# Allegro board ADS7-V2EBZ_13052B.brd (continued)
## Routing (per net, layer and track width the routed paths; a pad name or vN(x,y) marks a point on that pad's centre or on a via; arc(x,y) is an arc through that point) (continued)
UNNAMED_22_RES_I263_N2: length 4.7
  TOP w0.14: R52.2 201.55,142.37 v1(200.91,143)
  BOTTOM w0.14: v1(200.91,143) 199.64,143 198.5,144.15 Q11.3
UNNAMED_22_RES_I265_N2: length 1.8
  TOP w0.14: R61.2 v1(17.27,132.84)
  BOTTOM w0.14: Q12.3 v1(17.27,132.84)
UNNAMED_24_CAP_I8_N2: length 6.3
  BOTTOM w0.203: C164.2 90.52,126.81 U39.1 ; C164.2 90.81,126.71 90.81,128.52 ; C164.2 91.06,126.28 R232.2
UNNAMED_24_CAP_I26_N2: length 6.6
  TOP w0.14: C134.2 156.55,29.85 158.37,29.85 158.64,30.12 U35.1 ; C134.2 155.96,29.76 R177.2 ; C134.2 156.21,30.19 R664.2
UNNAMED_24_ICTPS51200_I1_EN: length 4.8
  BOTTOM w0.14: R222.1 R559.2 R558.1 86.88,130.8 U39.7
UNNAMED_24_ICTPS51200_I33_EN: length 5.3
  TOP w0.14: R658.2 R170.1 R660.1 160.14,34.28 U35.7
UNNAMED_25_74LVC1G17_I357_A: length 8.2
  TOP w0.14: v1(171.45,121.54) 171.96,121.54 CR1.C
  BOTTOM w0.14: 172.47,120.52 172.47,119.8 R233.1 ; 172.47,120.52 v1(171.45,121.54) R224.2 ; 172.47,120.52 U40.2
UNNAMED_25_CAP_I36_N2: length 13.1
  TOP w0.14: C142.2 S6.3 S6.4 105.92,18.62 R193.1 104.27,21.08
UNNAMED_25_CAP_I49_N2: length 9
  BOTTOM w0.14: S3.4 105.87,28.7 R191.1 C141.2 ; C141.2 101.47,27.3 100.71,26.54 ; C141.2 99.51,28.7 S3.3
UNNAMED_25_CAP_I423_N2: length 13.9
  TOP w0.14: R175.2 207.77,34.29 208.66,35.18 208.66,37.34 R169.1 C130.2 R168.2 204.09,39.12 U33.6
UNNAMED_25_CN3P_I305_N1: length 8.3
  TOP w0.14: D3.A 163.53,125.78 163.7,125.6 P4.1
  BOTTOM w0.14: Q13.3 163.58,123.95 P4.1
UNNAMED_25_CN3P_I305_N3: length 4.2
  BOTTOM w0.14: P4.3 168.91,123.95 R224.1 R234.2
UNNAMED_25_CNBNC5P_I329_CNTR: length 4.1
  TOP w0.14: R151.2 J6.1
UNNAMED_25_CNBNC5P_I336_CNTR: length 5.5
  TOP w0.14: 207.14,75.95 J5.1
UNNAMED_25_CNBNC5P_I370_CNTR: length 8.6
  TOP w0.14: J3.1 209.42,45.47 208.66,44.7 C127.2
UNNAMED_25_CNBNC5P_I378_CNTR: length 4.8
  TOP w0.14: J4.1 R175.1
UNNAMED_25_DIOLED_I452_P: length 1.7
  TOP w0.14: R176.1 DS8.A
UNNAMED_25_DIOLED_I458_P: length 1.7
  TOP w0.14: R203.1 DS1.A
UNNAMED_25_DIOLED_I459_P: length 1.7
  TOP w0.14: R202.1 DS2.A
UNNAMED_25_DIOLED_I460_P: length 1.7
  TOP w0.14: R201.1 DS3.A
UNNAMED_25_DIOLED_I461_P: length 1.7
  TOP w0.14: R196.1 DS4.A
UNNAMED_25_DIOLED_I462_P: length 1.7
  TOP w0.14: R195.1 DS5.A
UNNAMED_25_DIOLED_I463_P: length 1.7
  TOP w0.14: DS6.A R194.1
UNNAMED_25_ICFXL4245_I446_B7: length 73.5
  TOP w0.14: v1(155.57,14.99) 155.57,15.75 155.31,16.01 U37.14 ; v1(89.66,25.15) R176.2
  L3_SIGNAL w0.095: v1(155.57,14.99) 119,14.99 117.98,13.97 109.86,13.97 107.19,16.64 103,16.64 96.27,23.37 92.96,23.37 91.19,25.15 v1(89.66,25.15)
UNNAMED_25_ICICS85411_I427_NQ0: length 3.7
  TOP w0.102: U33.2 195.94,40.39 195.45,40.87 194.89,40.87 194.42,41.34 194.25,41.34 R162.1
UNNAMED_25_ICICS85411_I427_NQ1: length 3.7
  TOP w0.102: U33.4 195.99,37.85 195.47,38.37 195.18,38.37 194.79,37.97 194.44,37.97 R167.1
UNNAMED_25_ICICS85411_I427_Q0: length 3.7
  TOP w0.102: R161.1 194.27,41.57 194.51,41.57 194.99,41.1 195.4,41.1 195.96,41.66 U33.1
UNNAMED_25_ICICS85411_I427_Q1: length 3.6
  TOP w0.102: R166.1 194.21,38.2 194.69,38.2 195.08,38.6 195.44,38.6 195.96,39.12 U33.3
UNNAMED_25_NC7WZ04P6X_I339_A1: length 10.1
  TOP w0.14: R142.2 R144.2 R145.1 207.14,68.45 208.28,67.31 208.28,65.1 U30.1
UNNAMED_25_NC7WZ04P6X_I339_Y2: length 2.7
  TOP w0.14: R151.1 207.26,61.37 207,61.64 U30.4
UNNAMED_25_RES_I367_N2: length 5.6
  TOP w0.14: U33.7 R163.2 R164.1 207.39,40.39
UNNAMED_28_ICPCA9545_I1_A0: length 3.1
  TOP w0.14: U36.1 185.42,24.13 185.93,23.62 R200.2
UNNAMED_28_ICPCA9545_I1_A1: length 6
  TOP w0.14: U36.2 185.66,24.78 186.06,24.38 190.12,24.38 R189.2
UNNAMED_28_ICPCA9545_I1_INT0N: length 5.9
  TOP w0.14: U36.4 185.76,26.08 185.93,25.91 R188.1
UNNAMED_28_ICPCA9545_I1_INT1N: length 3.1
  TOP w0.14: U36.7 185.38,28.03 185.8,28.45 R183.1
UNNAMED_28_ICPCA9545_I1_INT2N: length 6.3
  TOP w0.14: U36.11 177.8,29.98 176.91,30.86 172.85,30.86 R171.1
UNNAMED_28_ICPCA9545_I1_INT3N: length 3
  TOP w0.14: U36.14 176.7,28.03 176.4,28.32 R181.1
UNNAMED_28_ICPCA9545_I1_INTN: length 6
  TOP w0.14: R180.1 176.78,25.78 177.08,26.08 U36.17
UNNAMED_28_ICPCA9545_I1_SC1: length 3.2
  TOP w0.14: R173.1 186.18,30.1 185.42,29.34 185.42,29.33 U36.9
UNNAMED_28_ICPCA9545_I1_SD1: length 6.1
  TOP w0.14: U36.8 185.42,28.68 185.8,29.06 190.1,29.06 R186.1
USB_D_N: length 32.5
  TOP w0.102: v1(188.28,75.69) U29.F20
  L3_SIGNAL w0.089: P8.2 204.85,91.23 204.85,91.44 204.64,91.65 203.03,91.65 202.44,91.06 202.44,88.27 197.74,83.57 190.75,83.57 188,80.82 188,75.96 v1(188.28,75.69)
  BOTTOM w0.102: CR5.1 P8.2
USB_D_P: length 33.4
  TOP w0.102: U29.E20 v1(187.48,75.69)
  L3_SIGNAL w0.089: P8.3 205.91,90.34 205.1,91.14 205.1,91.55 204.75,91.9 202.92,91.9 202.18,91.16 202.18,88.37 197.63,83.82 190.65,83.82 187.75,80.92 187.75,75.96 v1(187.48,75.69)
  BOTTOM w0.102: CR4.1 205.99,90.3 P8.3
VRN_16: length 20.3
  TOP w0.14: v1(68.69,64.04) U31.V23
  BOTTOM w0.14: R251.1 70.99,76.33 70.14,75.48 70.14,64.85 69.88,64.59 69.24,64.59 v1(68.69,64.04)
VRN_17: length 20.9
  TOP w0.14: v1(62.69,64.04) U31.N23
  BOTTOM w0.14: R253.1 65.15,81.28 64.77,80.9 64.77,75.69 65.24,75.22 65.24,74.85 65.24,74.85 65.24,73.11 65.14,73.02 65.14,72.85 64.88,72.59 64.6,72.59 64.24,72.23 64.24,71.95 63.88,71.59 63.6,71.59 63.24,71.23 63.24,64.51 62.77,64.04 v1(62.69,64.04)
VRN_18: length 15.7
  TOP w0.14: v1(57.69,68.04) U31.H27
  BOTTOM w0.14: v1(57.69,68.04) 58.17,68.51 58.17,75.69 58.42,75.95 58.42,80.39 59.18,81.15 R255.1
VRN_19: length 13.2
  TOP w0.14: v1(55.69,65.04) U31.F24
  BOTTOM w0.14: v1(55.69,65.04) 56.14,65.49 56.14,75.81 55.63,76.33 R271.1
VRN_34: length 18.9
  TOP w0.14: v1(73.69,52.04) U31.AC12
  BOTTOM w0.14: v1(73.69,52.04) 74.17,51.56 85.09,51.56 85.6,51.05 R298.1
VRN_35: length 17
  TOP w0.14: v1(75.69,59.04) U31.AE18
  BOTTOM w0.14: R292.1 90.55,58.8 89.66,59.69 84.98,59.69 84.88,59.59 76.24,59.59 v1(75.69,59.04)
VRN_36: length 22
  TOP w0.14: v1(73.69,63.04) U31.AC22
  BOTTOM w0.14: R249.1 77.72,78.11 75.14,75.52 75.14,63.85 74.88,63.59 74.24,63.59 v1(73.69,63.04)
VRN_37: length 14
  TOP w0.14: v1(57.69,59.04) U31.H18
  BOTTOM w0.14: v1(57.69,59.04) 57.14,59.59 49.28,59.59 49.05,59.82 R283.1
VRN_38: length 17.5
  TOP w0.14: v1(60.69,56.04) U31.L16
  BOTTOM w0.14: R294.1 46.86,57.91 48.26,56.52 60.22,56.52 v1(60.69,56.04)
VRN_39: length 14.9
  TOP w0.14: v1(57.69,53.04) U31.H13
  BOTTOM w0.14: v1(57.69,53.04) 57.14,53.59 48.52,53.59 46.1,56.01 R295.1
VRP_16: length 19.1
  TOP w0.14: v1(72.69,66.04) U31.AB25
  BOTTOM w0.14: v1(72.69,66.04) 72.14,66.59 71.5,66.59 71.14,66.95 71.14,73.3 71.37,73.53 71.89,73.53 72.14,73.79 72.14,75.57 73.03,76.45 R250.2
VRP_17: length 21.7
  TOP w0.14: v1(66.69,64.04) U31.U23
  BOTTOM w0.14: R252.2 67.06,76.84 68.4,75.49 68.88,75.49 69.14,75.23 69.14,65.85 68.88,65.59 68.24,65.59 v1(66.69,64.04)
VRP_18: length 14.8
  TOP w0.14: v1(61.69,69.04) U31.M28
  BOTTOM w0.14: R254.2 61.09,80.77 61.72,80.14 61.72,75.68 62.2,75.2 62.2,69.55 v1(61.69,69.04)
VRP_19: length 11.9
  TOP w0.14: v1(58.69,67.04) U31.J26
  BOTTOM w0.14: R270.2 57.4,75.82 57.15,75.56 57.15,67.94 57.5,67.59 58.14,67.59 v1(58.69,67.04)
VRP_34: length 13.9
  TOP w0.14: v1(78.69,53.04) U31.AH13
  BOTTOM w0.14: R297.2 86.49,52.96 85.96,53.49 79.14,53.49 v1(78.69,53.04)
VRP_35: length 19.4
  TOP w0.14: v1(73.69,55.04) U31.AC15
  BOTTOM w0.14: R293.2 85.73,56.9 85.34,56.52 75.43,56.52 75.14,56.23 75.14,55.85 74.88,55.59 74.24,55.59 v1(73.69,55.04)
VRP_36: length 27.1
  TOP w0.14: v1(73.69,59.04) U31.AC18
  BOTTOM w0.14: R248.2 79.63,78.99 76.14,75.51 76.14,60.85 75.88,60.59 75.5,60.59 75.14,60.23 75.14,59.85 74.88,59.59 74.24,59.59 v1(73.69,59.04)
VRP_37: length 16.1
  TOP w0.14: v1(60.69,62.04) U31.L21
  BOTTOM w0.14: R269.2 60.71,75.69 60.24,75.23 60.24,62.49 v1(60.69,62.04)
VRP_38: length 25.5
  TOP w0.14: v1(56.69,59.04) U31.G18
  BOTTOM w0.14: v1(56.69,59.04) 57.83,57.9 60.72,57.9 61.21,57.4 R312.2
VRP_39: length 11.3
  TOP w0.14: v1(59.69,48.04) U31.K8
  BOTTOM w0.14: R313.2 59.56,40 59.18,40.39 59.18,47.53 v1(59.69,48.04)
VTTDDR1: length 67.8
  TOP w0.33: 97.54,104.89 97.54,104.9 97.28,104.9 96.75,104.37 P6.203 96.75,102.13 v2(97.16,101.73) v2(97.16,100.97) ; 97.54,104.89 98.03,104.89 v2(98.55,105.41) ; 97.54,104.89 v2(97.52,104.89) ; v2(98.04,109.98) v2(97.41,109.98) 97.05,110.34 P6.204 97.05,112.93 v2(97.28,113.16) v2(97.92,113.16)
  L20_SIGNAL w0.33: v2(98.55,105.41) 98.03,104.89 v2(97.52,104.89) ; v2(97.28,113.16) v2(97.92,113.16) ; v2(97.16,101.73) v2(97.16,100.97) ; v2(97.41,109.98) v2(98.04,109.98)
  BOTTOM w0.203: CN15.6 93.09,106.29 v2(92.84,106.05) 92.59,106.29 CN15.7 ; CN17.7 101.48,113.66 v2(101.73,113.41) 101.98,113.66 CN17.6 ; CN5.7 74.05,106.29 v2(74.3,106.05) 74.54,106.29 CN5.6
  BOTTOM w0.254: CN5.5 75.05,106.56 v2(75.56,106.05) ; v2(99.31,101.98) 99.83,102.5 CN1.5 ; v2(100.46,107.06) 100.72,107.32 CN9.6 ; v2(103,113.41) 102.48,113.93 CN17.5 ; CN7.7 v2(99.57,111.88) ; CN7.8 99.96,112.38 v2(99.57,112.78) ; v2(100.46,113.41) 100.58,113.41 100.98,113.8 CN17.8 ; v2(100.46,108.71) 100.85,108.32 CN9.8 ; v2(99.31,104.39) 99.71,104 CN1.8 ; v2(99.31,102.74) 99.57,103 CN1.6 ; CN9.7 v2(100.46,107.82) ; CN15.5 93.59,106.56 v2(94.11,106.05) ; CN15.8 92.09,106.44 91.69,106.05 v2(91.57,106.05) ; CN5.8 73.54,106.44 73.15,106.05 v2(73.03,106.05) ; CN9.5 100.98,106.82 v2(100.46,106.3) ; CN1.7 v2(99.32,103.5) ; CN7.5 100.09,110.88 v2(99.57,110.36) ; v2(99.57,111.12) 99.83,111.38 CN7.6
  BOTTOM w0.305: U39.3 87.38,126.24 87,125.86 ; U39.5 86.38,126.25 86.11,125.98
  BOTTOM w0.508: CN1.7 100.52,103.5 ; CN17.5 102.78,114.11 ; CN7.7 100.77,111.88 ; 101.15,106.51 CN9.5 101.66,106.82 ; 88.52,106.44 C222.2 ; C222.2 89.1,107.06 ; C222.2 87.88,107.06 v2(87.76,106.93) ; C221.2 v2(96.52,106.43) ; C221.2 95.89,105.8 ; C221.2 95.3,106.43 ; CN15.7 92.59,107.25 ; 93.59,107.25 CN15.5 93.89,106.74 ; 101.66,108.32 CN9.8 101.15,108.62 ; CN7.6 100.77,111.38 ; 100.26,112.69 CN7.8 100.77,112.38 ; 104.39,105.03 C231.2 v2(103.31,104.2) ; C234.2 97.03,101.21 ; 97.41,113.59 97.41,114.17 96.79,114.17 ; 100.01,102.2 CN1.5 100.52,102.5 ; 81.24,124.46 C184.2 ; C184.2 82.42,125.44 ; C184.2 83.6,124.46 ; 100.67,114.11 CN17.8 ; C224.2 v2(78.87,106.81) ; 100.26,110.58 CN7.5 100.77,110.88 ; 100.01,104.31 CN1.8 100.52,104 ; C183.2 86.53,124.46 ; C183.2 84.16,124.46 ; C183.2 85.34,125.44 ; CN9.6 101.66,107.32 ; CN9.7 101.66,107.82 ; 78.32,124.46 C185.2 ; C185.2 79.5,125.44 ; C185.2 80.68,124.46 ; CN1.6 100.52,103 ; C225.2 v2(71.25,106.81) ; 91.78,106.74 CN15.8 92.09,107.25 ; C223.2 v2(80.64,108.39) ; v2(97.16,101.73) 97.1,101.78 ; CN15.6 93.09,107.25
  vias: v2(79.12,126.24) v2(80.39,126.24) v2(81.53,126.24) v2(82.55,126.24) v2(83.69,126.24) v2(84.71,126.24) v2(85.6,126.24)
VTTDDR2: length 53.6
  TOP w0.305: U35.5 160.64,29.48 160.66,29.46 ; 160.66,29.46 159.89,29.46 159.64,29.72 U35.3 ; 160.66,29.46 161.29,29.46
  TOP w0.33: v2(111.76,23.37) 111.89,23.5 v2(112.52,23.5) 112.92,23.9 P5.203 115.17,23.9 v2(115.7,23.37) ; v2(120.02,23.24) v2(120.78,23.24) 121.13,23.6 P5.204 123.72,23.6 v2(123.95,23.37) v2(123.95,22.48)
  TOP w0.508: 167.51,27.94 168.69,27.94 ; 167.51,27.94 167.51,28.92 ; 167.51,27.94 166.33,27.94 ; 160.49,27.94 161.67,27.94 ; 161.67,27.94 162.85,27.94 ; 161.67,27.94 161.67,28.92 ; 163.41,27.94 164.59,27.94 ; 164.59,27.94 165.77,27.94 ; 164.59,27.94 164.59,28.92
  BOTTOM w0.203: v2(122.43,21.21) 122.43,21.09 ; 122.43,21.09 122.68,20.84 CN2.7 ; 122.43,21.09 122.18,20.84 CN2.6 ; v2(121.28,21.21) 121.68,20.82 CN2.5 ; 116.97,57.66 116.96,57.66 v2(116.71,57.91) ; v2(123.44,21.21) 123.18,20.94 CN2.8 ; v2(115.19,21.34) 114.87,21.02 CN8.8 ; CN8.5 113.37,20.99 v2(113.03,21.34) ; CN10.5 118.5,18.91 v2(118.24,19.18) ; CN8.6 113.87,21.16 v2(114.05,21.34) 114.37,21.01 CN8.7 ; CN10.6 119,18.93 v2(119.25,19.18) 119.5,18.93 CN10.7 ; CN10.8 120,18.78 v2(120.4,19.18)
  BOTTOM w0.254: CN18.5 117.23,51.45 v2(116.71,50.93) ; CN6.6 116.97,57.66 ; CN18.6 116.97,51.95 v2(116.71,51.69) ; CN16.5 117.23,46.37 v2(116.71,45.85) ; CN16.7 v2(116.72,47.37) ; CN6.5 117.23,57.16 v2(116.71,56.64) ; v2(116.71,53.34) 117.11,52.95 CN18.8 ; CN16.8 117.11,47.87 v2(116.71,48.26) ; CN16.6 116.97,46.87 v2(116.71,46.61) ; v2(116.71,57.91) 116.96,58.16 CN6.7 ; v2(116.71,59.06) 117.11,58.66 CN6.8 ; CN18.7 v2(116.72,52.45)
  BOTTOM w0.33: v2(120.78,23.24) v2(120.02,23.24) ; v2(112.52,23.5) 111.89,23.5 v2(111.76,23.37) ; v2(115.7,23.37) v2(116.46,23.37) ; v2(123.95,23.37) v2(123.95,22.48)
  BOTTOM w0.508: C345.2 v2(123.95,23.37) 124.1,23.22 C344.2 ; C302.2 v2(117.48,48.89) ; v2(112.52,23.5) 113.28,22.73 C346.2 ; C283.2 v2(117.22,60.33) ; C331.2 v2(117.16,37.78) ; C319.2 v2(117.48,41.91) ; C347.2 v2(115,15.05)
  vias: v2(162.43,30.1) v2(163.45,30.1) v2(164.47,30.1) v2(165.48,30.1) v2(166.5,30.1) v2(167.51,30.1) v2(168.53,30.1)
VTTREF1: length 14.6
  TOP w0.203: v2(73.03,109.98) 73.65,110.61 P6.126 ; v1(63.69,68.04) U31.P27 ; v1(62.69,73.04) U31.N32
  TOP w0.254: v1(70.69,68.04) U31.Y27 ; v1(60.69,66.04) U31.L25 ; v1(58.69,73.04) U31.J32 ; v1(68.69,74.04) U31.V33
  TOP w0.305: P6.1 33.76,102.21 v2(33.27,101.73)
  BOTTOM w0.305: U39.6 v2(85.91,129.73)
  BOTTOM w0.508: C253.2 v2(65.66,76.33) ; C263.2 68.56,74.17 v1(68.69,74.04) ; C165.2 v2(84.58,128.65) ; C232.2 v2(33.27,101.73) ; C273.2 v1(67.69,69.04) ; C252.2 v2(68.71,76.33) ; C251.2 v2(71.75,76.33) ; C254.2 v2(62.61,76.33)
VTTREF2: length 14.3
  TOP w0.203: v2(120.78,47.62) 121.41,47 P5.126
  TOP w0.254: v1(74.69,61.04) U31.AD20 ; v1(77.69,53.04) U31.AG13 ; v1(83.69,57.04) U31.AN17 ; v1(83.69,64.04) U31.AN23 ; v1(74.69,51.04) U31.AD11 ; v1(83.69,52.04) U31.AN12
  TOP w0.305: P5.1 113,86.89 v2(112.52,87.38) ; U35.6 160.64,33.51 160.97,33.85 v2(161.48,33.85) ; v2(162.18,33.27) 162.69,33.27 162.81,33.15 C135.2
  BOTTOM w0.508: C285.2 85.74,62.99 v1(85.69,63.04) ; v1(83.69,57.04) 83.31,57.42 C293.2 ; C292.2 v1(85.69,58.04) ; 77.85,52.96 77.77,52.96 v1(77.69,53.04) ; C303.2 85.72,52.07 v1(85.69,52.04) ; C294.2 v1(76.72,58.04) ; C239.2 v2(112.52,87.38)
WR_RDY: length 133.5
  TOP w0.14: v1(82.69,68.04) U31.AM27 ; RN9.11 177.94,72.76 v1(177.55,73.15)
  L16_SIGNAL w0.095: v1(178.69,87.76) 178.18,88.27 177.67,88.27 176.66,89.28 170.81,89.28 169.8,88.27 153.42,88.27 149.61,92.08 129.79,92.08 129.29,92.58 112.14,92.58 107.7,88.14 107.7,83.82 102.87,78.99 92.08,78.99 90.68,77.6 89.03,77.6 87.25,75.82 87.25,71.25 85.6,69.6 84.58,69.6 84.42,69.44 84.42,69.27 83.84,68.69 83.29,68.69 82.69,68.09 v1(82.69,68.04)
  L18_SIGNAL w0.095: v1(178.69,87.76) 178.69,75.31 179.45,74.55 179.45,73.91 179.07,73.53 177.93,73.53 v1(177.55,73.15)
XTAL1_25MHZ_AD9577: length 15.2
  TOP w0.14: 124.97,111.25 125.15,111.07 Y1.1 126.8,111.07 127.89,109.98 132.97,109.98 134.49,111.51 134.49,113.16 R92.1 134.11,113.8 134.11,115.02 134.22,115.13 U12.8
XTAL2_25MHZ_AD9577: length 7.2
  TOP w0.14: U12.7 133.72,113.65 R92.2 131.83,113.28 C68.1 130.81,113.41 130.36,112.96 Y1.3

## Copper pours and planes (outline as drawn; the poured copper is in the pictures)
DGND on TOP (solid shape): 215.27,42.23 209.11,42.23 209.11,44.52 209.59,45 215.27,45
DGND on TOP (solid shape): 11.45,32.64 11.48,32.62 11.5,32.58 12.07,31.94 12.63,32.58 12.65,32.62 12.68,32.64 12.72,32.64 12.75,32.62 12.77,32.58 12.86,32.19 13.2,31.96 13.21,31.95 13.31,31.86 13.26,31.81 13.24,31.81 12.93,31.65 12.77,31.33 12.77,31.32 12.72,31.27 12.62,31.37 12.62,31.38 12.01,31.81 11.49,31.27 11.49,31.25 11.44,31.2 11.37,31.28 11.36,31.3 11.15,31.69 10.73,31.81 10.68,31.82 10.67,31.86 10.67,31.89 10.68,31.93 10.73,31.94 11.2,32.11 11.36,32.58 11.38,32.62 11.41,32.64
DGND on TOP (solid shape): 15.26,49.15 15.29,49.13 15.31,49.09 15.43,48.67 15.82,48.45 15.83,48.45 15.91,48.37 15.86,48.32 15.84,48.32 15.3,47.77 15.82,47.18 15.83,47.18 15.91,47.1 15.86,47.05 15.84,47.05 15.47,46.89 15.3,46.51 15.3,46.49 15.25,46.44 15.18,46.52 15.17,46.54 14.96,46.93 14.54,47.05 14.49,47.06 14.48,47.1 14.48,47.13 14.49,47.17 14.54,47.18 15.18,47.75 14.54,48.32 14.49,48.33 14.48,48.37 14.48,48.4 14.49,48.44 14.54,48.45 15.01,48.62 15.17,49.09 15.19,49.13 15.22,49.15
DGND on TOP (solid shape): 15.26,44.07 15.29,44.05 15.31,44.01 15.43,43.59 15.82,43.37 15.83,43.37 15.91,43.29 15.86,43.24 15.84,43.24 15.3,42.69 15.82,42.1 15.83,42.1 15.91,42.02 15.86,41.97 15.84,41.97 15.47,41.81 15.3,41.43 15.3,41.41 15.25,41.36 15.18,41.44 15.17,41.46 14.96,41.85 14.54,41.97 14.49,41.98 14.48,42.02 14.48,42.05 14.49,42.09 14.54,42.1 15.18,42.67 14.54,43.24 14.49,43.25 14.48,43.29 14.48,43.32 14.49,43.36 14.54,43.37 15.01,43.54 15.17,44.01 15.19,44.05 15.22,44.07
DGND on TOP (solid shape): 15.26,38.99 15.29,38.97 15.31,38.93 15.43,38.51 15.82,38.29 15.83,38.29 15.91,38.21 15.86,38.16 15.84,38.16 15.3,37.61 15.82,37.02 15.83,37.02 15.91,36.94 15.86,36.89 15.84,36.89 15.47,36.73 15.3,36.35 15.3,36.33 15.25,36.28 15.18,36.36 15.17,36.38 14.96,36.77 14.54,36.89 14.49,36.9 14.48,36.94 14.48,36.97 14.49,37.01 14.54,37.02 15.18,37.59 14.54,38.16 14.49,38.17 14.48,38.21 14.48,38.24 14.49,38.28 14.54,38.29 15.01,38.46 15.17,38.93 15.19,38.97 15.22,38.99
DGND on TOP (solid shape): 13.99,28.83 14.02,28.81 14.04,28.77 14.61,28.13 15.17,28.77 15.19,28.81 15.22,28.83 15.26,28.83 15.29,28.81 15.31,28.77 15.43,28.35 15.82,28.13 15.83,28.13 15.91,28.05 15.86,28 15.84,28 15.3,27.45 15.82,26.86 15.83,26.86 15.91,26.78 15.86,26.73 15.84,26.73 15.48,26.57 15.31,26.22 15.3,26.2 15.25,26.15 15.17,26.23 15.17,26.25 14.95,26.62 14.54,26.73 14.49,26.74 14.48,26.78 14.48,26.81 14.49,26.85 14.54,26.86 15.06,27.78 14.04,27.52 14.04,27.51 13.99,27.46 13.89,27.56 13.89,27.57 13.66,27.9 13.27,28 13.22,28.01 13.21,28.05 13.21,28.08 13.22,28.12 13.27,28.13 13.74,28.3 13.9,28.77 13.92,28.81 13.95,28.83
DGND on TOP (solid shape): 12.72,41.53 12.75,41.51 12.77,41.47 13.34,40.83 13.9,41.47 13.92,41.51 13.95,41.53 13.99,41.53 14.02,41.51 14.04,41.47 14.16,41.05 14.55,40.83 14.56,40.83 14.64,40.75 14.59,40.7 14.57,40.7 14.03,40.15 14.55,39.56 14.56,39.56 14.64,39.48 14.59,39.43 14.57,39.43 14.21,39.27 14.04,38.92 14.03,38.9 13.98,38.85 13.9,38.93 13.9,38.95 13.68,39.32 13.27,39.43 13.22,39.44 13.21,39.48 13.21,39.51 13.22,39.55 13.27,39.56 13.78,40.49 12.77,40.19 12.76,40.17 12.71,40.12 12.63,40.2 12.63,40.22 12.41,40.59 12,40.7 11.95,40.71 11.94,40.75 11.94,40.78 11.95,40.82 12,40.83 12.47,41 12.63,41.47 12.65,41.51 12.68,41.53
DGND on TOP (solid shape): 13.99,46.61 14.02,46.59 14.04,46.55 14.16,46.13 14.55,45.91 14.56,45.91 14.64,45.83 14.59,45.78 14.57,45.78 14.03,45.23 14.55,44.64 14.56,44.64 14.64,44.56 14.59,44.51 14.57,44.51 14.2,44.35 14.03,43.97 14.03,43.95 13.98,43.9 13.91,43.98 13.9,44 13.32,44.51 12.76,43.97 12.76,43.95 12.71,43.9 12.64,43.98 12.63,44 12.42,44.39 12,44.51 11.95,44.52 11.94,44.56 11.94,44.59 11.95,44.63 12,44.64 12.47,44.81 12.63,45.28 12.65,45.32 12.68,45.34 12.72,45.34 12.75,45.32 12.77,45.28 13.74,44.81 13.27,45.78 13.22,45.79 13.21,45.83 13.21,45.86 13.22,45.9 13.27,45.91 13.74,46.08 13.9,46.55 13.92,46.59 13.95,46.61
DGND on TOP (solid shape): 13.99,36.45 14.02,36.43 14.04,36.39 14.16,35.97 14.55,35.75 14.56,35.75 14.64,35.67 14.59,35.62 14.57,35.62 14.03,35.07 14.55,34.48 14.56,34.48 14.64,34.4 14.59,34.35 14.57,34.35 14.24,33.34 15.17,33.85 15.19,33.89 15.22,33.91 15.26,33.91 15.29,33.89 15.31,33.85 15.43,33.43 15.82,33.21 15.83,33.21 15.91,33.13 15.86,33.08 15.84,33.08 15.3,32.53 15.82,31.94 15.83,31.94 15.91,31.86 15.86,31.81 15.84,31.81 15.47,31.65 15.3,31.27 15.3,31.25 15.25,31.2 15.18,31.28 15.17,31.3 14.96,31.69 14.54,31.81 14.49,31.82 14.48,31.86 14.48,31.89 14.49,31.93 14.54,31.94 15.06,32.86 14.04,32.6 14.04,32.59 13.99,32.54 13.89,32.64 13.89,32.65 13.66,32.98 13.27,33.08 13.22,33.09 13.21,33.13 13.21,33.16 13.22,33.2 13.27,33.21 13.91,33.78 13.27,34.35 13.22,34.36 13.21,34.4 13.21,34.43 13.22,34.47 13.27,34.48 13.91,35.05 13.27,35.62 13.22,35.63 13.21,35.67 13.21,35.7 13.22,35.74 13.27,35.75 13.74,35.92 13.9,36.39 13.92,36.43 13.95,36.45
DGND on BOTTOM: 0.64,9.65 215.27,9.65 215.27,24.38 209.3,24.38 209.04,24.64 209.04,81.66 209.42,82.04 215.27,82.04 215.27,173.48 0.64,173.48 ; 6 cut-outs
DGND on L2_GROUND, L4_GROUND, L8_GROUND, L17_GROUND: 0.64,9.65 215.27,9.65 215.27,173.48 0.64,173.48
DGND on L6_GROUND, L10_GROUND, L15_GROUND: 0.64,173.48 0.64,9.65 215.27,9.65 215.27,173.48
DGND on L11_POWER: 115.95,125.35 135.38,125.35 135.38,52.96 177.42,52.96 183.26,58.8 208.41,58.8 210.19,60.58 210.19,73.15 209.42,73.91 209.42,107.31 209.3,107.44 178.56,107.44 178.56,120.65 188.09,120.65 188.09,116.97 214.63,116.97 214.63,10.29 115.95,10.29
DGND on L12_POWER: 1.27,10.29 1.27,33.27 25.27,33.27 25.27,37.85 87.25,37.85 87.25,44.2 112.39,44.2 112.39,26.67 110.24,24.51 110.24,20.83 111.38,19.68 132.59,19.68 134.87,21.97 168.66,21.97 171.2,24.51 171.2,36.07 171.07,36.19 123.44,36.19 123.44,60.83 131.32,60.83 144.4,73.91 153.29,73.91 154.18,73.03 156.21,73.03 157.1,73.91 168.66,73.91 173.35,78.61 173.35,116.97 214.63,116.97 214.63,10.29
DGND on L19_GROUND: 0.64,9.65 215.27,9.65 215.27,24.38 209.17,24.38 209.04,24.51 209.04,81.66 209.42,82.04 215.27,82.04 215.27,173.48 0.64,173.48
DGND on L21_GROUND: 0.64,9.65 215.27,9.65 215.27,24.38 209.3,24.38 209.04,24.64 209.04,81.66 209.42,82.04 215.27,82.04 215.27,173.48 0.64,173.48
DGND on L23_GROUND: 0.64,173.48 0.64,9.65 215.27,9.65 215.27,24.38 209.3,24.38 209.04,24.64 209.04,81.66 209.42,82.04 215.27,82.04 215.27,173.48
VCC1V5 on TOP: 89.28,163.45 96.65,163.45 97.03,163.07 97.03,160.02 96.77,159.77 96.77,156.08 96.39,155.7 90.04,155.7 88.9,156.84 88.9,163.07
VCC1V5 on L13_POWER: 38.99,10.29 38.99,17.65 36.83,19.81 32.64,19.81 27.81,24.64 27.94,43.43 24,47.37 24,81.79 18.54,87 18.54,92.96 19.3,93.47 19.3,104.39 19.68,104.78 19.68,114.81 21.72,114.81 22.86,115.95 22.86,135.76 1.27,135.76 1.27,172.85 51.69,172.85 51.69,165.99 52.96,164.72 166.5,164.72 166.62,74.42 166.62,38.86 155.32,38.86 155.32,30.23 160.91,30.23 160.91,25.4 150.37,25.4 150.37,10.29
VCC3V3 on TOP: 157.94,45.75 157.73,45.59 157.73,41.53 158.37,41.02 161.54,41.02 162.18,41.78 162.18,46.1 160.02,46.1 159.67,45.75
VCC3V3 on L12_POWER: 1.27,33.91 1.27,172.85 32,172.85 32,139.19 20.19,139.19 20.19,128.4 15.88,128.4 15.88,115.19 20.19,115.19 20.19,37.85 24.64,37.85 24.64,33.91
VCC3V3 on L14_POWER: 110.87,51.18 148.46,51.18 153.03,55.75 154.94,55.75 162.18,48.51 162.18,40.51 163.07,39.62 169.04,39.62 169.93,40.51 169.93,48.64 174.37,53.09 174.37,63.25 172.47,65.15 147.19,90.81 93.34,90.81 93.34,106.05 105.79,106.05 105.79,119.38 97.79,127.38 88.52,127.38 88.14,127.76 88.14,130.05 87,131.19 72.26,131.19 72.26,131.06 68.2,127 68.2,120.9 66.29,119 30.48,119 30.1,119.38 30.1,141.35 13.84,141.35 13.84,145.67 26.67,145.67 27.18,146.18 27.18,172.85 214.63,172.85 214.63,10.29 110.87,10.29
VIN on TOP: 191.01,134.37 190.12,133.48 178.18,133.48 177.16,134.49 177.16,147.96 178.44,149.22 181.48,149.22 181.99,148.72 181.99,146.81 182.12,146.69 183.01,146.69 183.64,146.05 183.64,143.51 184.91,142.24 187.45,142.24 188.21,141.48 188.21,140.21 188.47,139.95 190.75,139.95 191.01,139.7
VIN on L5_SIGNAL: 177.55,144.91 177.55,147.32 182.5,152.27 204.34,152.27 205.49,151.13 205.49,144.91 204.72,144.15 178.31,144.15
VIN_12V on TOP: 129.54,160.78 129.54,158.62 132.97,158.62 132.97,160.78
VIN_12V on TOP: 50.42,155.45 50.42,153.42 49.91,152.91 47.5,152.91 46.74,153.67 46.74,154.81 48.39,156.46 48.77,156.46 49.66,155.57 49.66,155.45
VIN_12V on TOP: 58.42,160.78 58.42,158.62 61.85,158.62 61.85,160.78
VIN_12V on TOP: 158.88,69.72 156.84,69.72 156.34,70.23 156.34,72.64 157.1,73.41 158.24,73.41 159.89,71.76 159.89,71.37 159,70.48 158.88,70.48
VIN_12V on TOP: 119.76,166.37 121.92,166.37 122.3,165.99 122.3,164.08 122.05,163.83 120.27,163.83 119.38,164.72 119.38,165.99
VIN_12V on TOP: 48.64,166.37 50.8,166.37 51.18,165.99 51.18,164.08 50.93,163.83 49.15,163.83 48.26,164.72 48.26,165.99
VIN_12V on TOP: 121.54,155.45 121.54,153.42 121.03,152.91 118.62,152.91 117.86,153.67 117.86,154.81 119.51,156.46 119.89,156.46 120.78,155.57 120.78,155.45
VIN_12V on TOP: 169.8,71.5 169.8,69.34 169.42,68.96 167.51,68.96 167.26,69.22 167.26,70.99 168.15,71.88 169.42,71.88
VIN_12V on TOP: 169.04,147.96 167.51,149.48 167.51,159.38 169.55,161.42 174.88,161.42 175.39,160.91 175.39,157.1 175.13,156.84 172.97,156.84 172.47,156.34 172.47,152.02 176.15,148.34 176.15,135.13 174.88,133.86 171.7,133.86 170.05,135.51 170.05,140.21 169.04,141.22
VIN_12V on L11_POWER: 146.18,57.28 146.18,149.35 104.78,149.35 104.39,149.73 104.39,172.85 214.63,172.85 214.63,143.64 188.21,143.64 188.21,121.41 176.53,121.41 173.86,118.75 170.18,118.75 169.55,119.38 169.55,120.78 168.53,121.79 166.75,121.79 166.12,121.16 166.12,112.01 173.61,104.52 173.61,57.28
VIN_12V on L12_POWER: 76.2,150.5 35.56,150.5 35.56,135 23.49,135 23.49,115.7 16.51,115.7 16.51,127.76 20.7,127.76 20.83,127.89 20.83,138.56 32.64,138.56 32.64,172.85 214.63,172.85 214.63,117.6 158.12,117.6 158.12,166.12 156.34,167.89 93.6,167.89
(no net) on TOP: 0.64,9.65 215.27,9.65 215.27,173.48 0.64,173.48
ADP5054_#1_SENSE1 on TOP: 157.23,94.36 157.23,87.88 156.72,87.38 155.57,87.38 155.07,86.87 155.07,85.34 155.45,84.96 171.32,84.96 171.58,85.22 171.58,86.87 171.07,87.38 169.93,87.38 169.29,88.01 169.29,94.36 169.16,94.49 157.35,94.49
ADP5054_#1_SENSE3 on TOP: 162.56,47.12 161.04,47.12 160.78,47.37 159.77,47.37 159.64,47.5 154.43,47.5 153.54,48.39 153.54,58.29 159,58.29 159,49.78 162.56,49.78
ADP5054_#1_SENSE4 on TOP: 170.94,58.29 170.94,48.26 170.18,47.5 165.48,47.5 165.1,47.12 163.45,47.12 163.45,49.78 167.26,49.78 167.26,58.29
ADP5054_#1_VREG on L12_POWER: 155.96,69.47 155.96,62.87 171.7,62.87 171.7,69.47
ADP5054_#2_SENSE1 on TOP: 98.17,165.23 98.17,154.31 98.68,153.8 106.55,153.8 107.31,154.56 107.31,164.97 106.43,165.86 98.81,165.86
ADP5054_#2_SENSE3 on TOP: 143.89,154.31 142.75,153.16 132.97,153.16 132.97,155.57 141.48,155.57 141.48,163.83 132.97,163.83 132.97,166.62 141.73,166.62 143.89,164.47
ADP5054_#3_SENSE1 on TOP: 28.07,155.32 28.07,149.99 28.57,149.48 36.45,149.48 37.21,150.24 37.21,155.07 36.96,155.32
ADP5054_#3_SENSE2 on TOP: 37.08,165.99 37.72,166.62 37.72,170.56 37.59,170.69 28.13,170.69 27.88,170.43 27.88,166.18 28.07,165.99
ADP5054_#3_SENSE3 on TOP: 73.03,158.12 73.03,157.48 72.52,156.97 72.52,152.91 71.5,151.89 61.85,151.89 61.85,155.57 70.36,155.57 70.36,158.12
ADP5054_#3_SENSE4 on TOP: 61.98,167.64 72.01,167.64 73.15,166.5 73.15,161.8 72.64,161.29 72.64,160.27 72.14,159.77 70.48,159.77 70.48,163.96 61.98,163.96
BF_VCC1V2 on L11_POWER: 178.56,106.81 178.56,67.56 200.41,67.56 208.79,75.95 208.79,106.81
BF_VCC1V8 on L13_POWER: 151,10.29 151,24.64 161.54,24.64 161.54,30.86 155.96,30.86 155.96,38.23 167.26,38.23 167.26,165.35 53.09,165.35 52.32,166.12 52.32,172.85 214.63,172.85 214.63,10.29
BF_VCC2V5 on L12_POWER: 184.02,108.2 184.02,71.76 204.85,71.76 204.85,108.2
FMC-1_VIO_B_M2C on TOP (solid shape): 15.36,102.81 15.6,102.81 15.6,103.75 16.01,103.75 16.01,102.81 16.25,102.81 16.25,103.75 16.66,103.75 16.66,102.81 16.9,102.81 16.9,103.75 17.31,103.75 17.31,101.11 14.95,101.11 14.95,103.75 15.36,103.75
FMC-1_VIO_B_M2C on TOP: 10.67,106.81 10.67,103.89 17.4,103.89 17.4,106.81
FMC-1_VIO_B_M2C on L13_POWER: 20.45,27.69 20.45,34.54 5.71,34.54 5.59,114.68 5.59,114.81 19.05,114.81 19.05,105.79 17.91,104.65 17.91,95 16.89,94.11 16.89,89.79 16,88.9 16,85.85 21.72,80.26 21.72,46.86 25.78,42.8 25.91,23.62 25.91,22.48 26.16,22.22 26.8,22.22 27.18,22.73 27.94,22.73 32,18.54 36.32,18.54 37.08,17.78 37.08,15.24 37.47,14.99 38.23,14.99 38.23,10.29 1.27,10.29 1.27,27.69
FMC-1_VIO_B_M2C_S on TOP: 11.56,101.09 14.22,101.09 14.73,100.58 14.73,99.44 16.38,99.44 16.64,99.19 16.64,97.54 15.88,96.77 11.81,96.77 11.68,96.9 11.68,98.81 11.18,99.31 11.18,100.71
FMC-1_VIO_B_M2C_S on L11_POWER: 13.91,93.92 12.7,95.12 12.7,98.55 14.35,100.2 15.75,100.2 18.03,97.92 22.22,97.92 24.51,100.2 37.47,100.2 58.17,79.5 58.17,65.79 55.88,63.5 52.45,63.5 49.66,66.29 49.66,75.06 30.8,93.92
FMC_1V8 on TOP: 15.37,166.88 14.22,168.02 14.22,170.31 14.86,170.94 26.16,170.94 26.54,170.56 26.54,167.51 25.91,166.88
FMC_1V8 on L14_POWER: 1.27,24.51 1.27,172.85 26.42,172.85 26.42,146.81 26.04,146.43 13.72,146.43 13.34,146.05 13.34,140.72 29.46,140.72 29.46,97.79 46.23,97.92 46.23,65.28 55.12,65.28 55.37,65.02 62.36,65.02 62.36,41.78 26.04,41.78 23.75,39.5 23.75,24.51
FMC_3V3 on TOP: 13.72,149.99 13.34,150.37 13.34,153.42 13.97,154.05 25.65,154.05 26.54,153.16 26.54,150.5 26.04,149.99
FMC_3V3 on L11_POWER: 1.27,10.29 1.27,172.85 41.78,172.85 42.42,172.21 42.42,146.05 41.78,145.41 23.37,145.41 23.37,99.95 21.84,98.42 18.67,98.42 16.26,100.84 13.34,100.84 12.07,99.57 12.07,94.62 13.34,93.34 19.43,93.34 20.83,91.95 20.83,25.02 38.73,25.02 38.73,10.29
FMC_12V0 on L13_POWER: 1.27,28.32 1.27,135.13 22.22,135.13 22.22,116.2 21.46,115.44 4.95,115.44 4.95,33.78 19.81,33.78 19.81,28.32
FPGA_1V0 on TOP: 166.75,103.63 166.75,96.27 166.37,95.89 159.64,95.89 159,96.52 159,102.87 160.15,104.01 166.37,104.01
FPGA_1V0 on L12_POWER: 61.21,48.01 61.21,64.9 70.87,64.9 74.93,68.96 74.93,96.14 152.91,96.14 156.59,99.82 156.59,115.44 158.12,116.97 172.72,116.97 172.72,78.99 168.28,74.55 156.84,74.55 155.96,73.66 154.56,73.66 153.67,74.55 143.89,74.55 130.94,61.59 112.39,61.59 112.39,44.7 87.25,44.7 87.25,47.37 86.61,48.01
FPGA_1V0_MGT on TOP: 154.56,164.34 154.56,152.91 145.41,152.91 145.41,158.88 144.91,159.38 144.91,164.34
FPGA_1V0_MGT on L12_POWER: 20.83,38.35 20.83,115.06 24.13,115.06 24.13,134.37 36.2,134.37 36.2,149.86 76.71,149.86 93.98,167 156.21,167.13 157.48,165.86 157.48,117.47 155.83,115.82 155.83,100.08 152.53,96.77 74.3,96.77 74.3,69.6 70.36,65.66 60.58,65.66 60.58,48.51 86.74,48.51 86.74,38.48 31.75,38.48 31.75,38.35
FPGA_1V2_MGT on TOP: 73.66,161.54 73.66,165.48 80.39,165.48 80.39,160.66 74.55,160.66
FPGA_1V2_MGT on L11_POWER: 49.66,45.21 53.47,49.02 76.58,49.02 80.52,52.96 80.52,78.11 72.01,86.61 72.01,137.67 83.82,149.48 83.82,157.35 81.28,159.89 72.01,159.89 72.01,172.85 103.76,172.85 103.76,149.73 104.78,148.72 115.19,148.72 115.19,10.29 49.66,10.29
FPGA_1V8 on TOP: 164.08,46.36 163.45,45.85 163.45,41.78 164.08,41.28 167.26,41.28 167.89,42.04 167.89,46.1 165.23,46.1 164.97,46.36
FPGA_1V8 on L11_POWER: 136.14,53.47 136.14,125.98 115.95,125.98 115.95,148.72 145.54,148.72 145.54,56.64 174.12,56.64 174.24,56.77 174.24,104.65 166.75,112.14 166.75,120.78 167,121.03 168.15,121.03 168.66,120.52 168.66,119.13 169.55,118.24 174.24,118.24 176.53,120.52 177.55,120.52 177.93,120.14 177.93,66.67 201.04,66.67 207.65,73.28 209.04,73.28 209.55,72.77 209.55,60.96 208.03,59.44 182.88,59.44 176.91,53.47
FPGA_1V8 on L14_POWER: 26.29,10.29 1.27,10.41 1.27,23.88 24.38,23.88 24.38,39.24 26.29,41.15 62.1,41.15 62.1,40.64 63.12,40.64 63.12,65.02 69.22,65.02 72.9,68.71 72.9,100.58 92.71,100.58 92.71,89.92 146.56,89.92 173.61,62.87 173.61,53.34 169.29,49.02 169.29,41.02 168.53,40.26 163.32,40.26 162.81,40.77 162.81,48.89 155.32,56.39 152.53,56.39 147.83,51.69 110.24,51.69 110.24,10.29
FPGA_2V0 on TOP: 73.79,158.37 73.79,157.23 74.04,156.97 74.04,151.89 80.39,151.89 80.39,158.37
FPGA_2V0 on L11_POWER: 48.9,66.17 52.07,62.99 56.26,62.99 58.8,65.53 58.8,79.76 37.85,100.71 23.88,100.71 23.88,144.65 24,144.78 42.29,144.78 43.05,145.54 43.05,172.85 71.25,172.85 71.25,159.26 81.15,159.26 83.19,157.23 83.19,149.73 71.37,137.92 71.37,86.23 79.88,77.72 79.88,53.21 77.09,50.42 76.96,50.42 76.2,49.66 53.47,49.66 49.02,45.21 49.02,10.29 39.37,10.29 39.37,25.65 21.46,25.65 21.46,93.22 30.61,93.22 48.9,74.93
UNNAMED_15_CAP_I13_N2 on TOP: 160.02,74.42 160.02,78.87 160.66,79.5 162.81,79.5 162.94,79.63 162.94,82.93 157.35,82.93 156.72,82.3 156.72,80.64 158.18,79.18 158.18,74.1 160.53,71.76 160.91,71.76 161.04,71.63 161.04,71.56 161.86,71.56 162.05,71.76 162.05,72.01 161.93,72.14 161.29,72.14 161.16,72.26 161.16,73.28
UNNAMED_15_CAP_I14_N2 on TOP: 164.85,71.63 164.85,72.01 164.97,72.14 165.48,72.14 165.61,72.26 165.61,72.77 165.54,72.83 165.54,73.22 166.75,74.42 166.75,78.99 166.24,79.5 163.83,79.5 163.7,79.63 163.7,82.93 168.91,82.93 169.67,82.17 169.67,80.52 168.28,79.12 168.28,72.9 167,71.63
UNNAMED_20_ADP5054_I24_SW11 on TOP: 116.84,156.59 112.39,156.59 111.76,157.23 111.76,159.38 111.63,159.51 109.6,159.51 109.6,153.29 115.7,153.29 119.51,157.1 119.51,157.48 119.63,157.61 119.7,157.61 119.7,158.43 119.51,158.62 119.25,158.62 119.13,158.5 119.13,157.86 119,157.73 117.98,157.73
UNNAMED_20_ADP5054_I24_SW21 on TOP: 119.63,161.42 119.25,161.42 119.13,161.54 119.13,162.05 119,162.18 118.49,162.18 118.43,162.12 118.05,162.12 116.84,163.32 112.27,163.32 111.76,162.81 111.76,160.4 111.63,160.27 109.6,160.27 109.6,166.12 109.73,166.24 116.97,166.24 119.63,163.58
UNNAMED_21_ADP5054_I24_SW11 on TOP: 45.72,156.59 41.28,156.59 40.64,157.23 40.64,159.38 40.51,159.51 36.83,159.51 36.83,156.84 36.96,156.72 39.12,156.72 40.01,155.83 40.01,149.86 40.39,149.48 42.29,149.48 45.72,152.91 45.72,154.43 48.39,157.1 48.39,157.48 48.51,157.61 48.58,157.61 48.58,158.43 48.39,158.62 48.13,158.62 48.01,158.5 48.01,157.86 47.88,157.73 46.86,157.73
UNNAMED_21_ADP5054_I24_SW21 on TOP: 48.51,161.42 48.13,161.42 48.01,161.54 48.01,162.05 47.88,162.18 47.37,162.18 47.31,162.12 46.93,162.12 45.72,163.32 41.15,163.32 40.64,162.81 40.64,161.67 40.39,161.42 36.83,161.42 36.83,163.45 39.37,163.45 40.13,164.21 40.13,166.24 40.01,166.37 40.01,169.16 40.89,170.05 42.04,170.05 48.51,163.58
UNNAMED_22_ADM1178_I115_SENSE on TOP (solid shape): 15.53,119.27 15.12,119.27 15.12,120.2 14.88,120.2 14.88,119.27 14.47,119.27 14.47,120.2 14.23,120.2 14.23,119.27 13.82,119.27 13.82,120.2 13.58,120.2 13.58,119.27 13.17,119.27 13.17,121.91 15.53,121.91
UNNAMED_22_ADM1178_I115_SENSE on TOP: 13.59,119 15.62,119 15.75,119.13 15.75,120.14 16.13,120.52 17.91,120.52 18.29,120.9 18.29,121.67 18.41,121.79 18.41,122.05 18.54,122.17 18.67,122.05 18.67,121.79 18.92,121.54 18.92,119.25 18.67,119 17.4,119 16.38,117.98 13.21,117.98 13.08,118.11 13.08,119 13.21,119.13 13.46,119.13
UNNAMED_22_CN6P_I262_N1 on L11_POWER: 214.63,143 214.63,117.6 188.85,117.6 188.85,143
UNNAMED_22_FSFUSE_I289_N1 on TOP: 192.91,133.22 193.68,132.46 202.69,132.46 203.33,133.1 203.33,135.64 202.56,136.4 197.49,136.4 196.6,137.29 193.68,137.29 192.91,136.53
UNNAMED_22_RES_I206_N2 on TOP: 175.77,160.4 175.77,153.54 176.53,152.78 180.97,152.78 181.48,153.29 181.48,155.07 180.97,155.57 180.97,160.4
VTTDDR1 on BOTTOM: 78.87,126.75 85.47,126.75 85.98,126.24 87.12,126.24 87.38,125.98 87.38,125.73 86.74,125.09 86.74,123.82 86.61,123.7 78.49,123.7 78.23,123.95 78.23,126.11
VTTDDR1 on BOTTOM: 93.98,111.63 85.98,111.63 85.09,110.74 85.09,106.43 90.81,100.71 99.82,100.71 102.74,103.63 104.9,103.63 105.41,104.14 105.41,112.01 103,114.43 96.77,114.43
VTTDDR1 on L14_POWER: 68.96,101.22 68.96,108.08 76.07,108.08 76.07,124.33 78.49,126.75 97.54,126.75 105.28,119 105.28,101.22
VTTDDR1 on L22_SIGNAL: 76.33,120.65 86.87,120.65 90.42,117.09 103.38,117.09 105.16,115.32 105.16,101.6 103.63,100.08 74.68,100.08 70.61,104.14 70.61,108.33 71.25,108.97 71.25,115.57
VTTDDR2 on TOP: 161.16,30.86 161.16,29.59 159.77,29.59 159.77,29.08 160.15,28.7 160.15,27.69 160.53,27.3 169.29,27.3 169.29,30.86
VTTDDR2 on L12_POWER: 113.16,60.83 113.16,26.54 110.74,24.13 110.74,21.21 111.63,20.32 132.08,20.32 134.37,22.61 168.02,22.61 170.43,25.02 170.43,35.31 122.56,35.31 122.56,60.83
VTTDDR2 on L16_SIGNAL: 111.38,25.27 125.6,25.27 127.25,23.62 127.25,16.64 125.09,14.48 114.3,14.48 111.12,17.65 111.12,25.02
VTTREF1 on L14_POWER: 55.63,65.53 55.37,65.79 46.86,65.79 46.86,98.55 30.1,98.55 30.1,118.36 66.55,118.36 68.83,120.65 68.83,126.62 72.64,130.43 81.79,130.43 81.85,130.37 84.26,130.37 84.33,130.43 86.61,130.43 87,130.05 87,127.76 86.61,127.38 77.85,127.38 75.31,124.84 75.31,108.71 67.95,108.71 67.95,100.71 72.39,100.71 72.39,68.96 68.96,65.53
VTTREF2 on L7_SIGNAL: 162.05,32.39 148.72,45.72 108.97,45.72 103.89,50.8 83.44,50.8 82.68,51.56 82.68,52.2 83.06,52.58 110.36,52.58 111.51,53.72 111.51,78.87 111.76,78.87 113.03,80.14 113.03,85.73 112.39,86.36 111.51,86.36 111.51,89.03 115.06,89.03 115.06,87.25 117.86,84.45 117.86,80.9 118.62,80.14 121.28,80.14 121.28,50.8 122.94,49.15 148.08,49.15 163.32,33.91 163.32,33.15 162.56,32.39
VTTREF2 on L20_SIGNAL: 76.58,64.14 84.96,64.14 86.49,62.61 86.49,51.69 85.34,50.55 74.17,50.55 74.17,61.72

Small or netless copper shapes (teardrops, artwork), in the pictures only: 34 on TOP

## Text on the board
Ref Des/Silkscreen Top: FMC_12V OVERCURRENT | SODIMM_1 | 0 | GND | 1 | 2 | 3 | 4 | SODIMM_2 | FPGA_DONE | FPGA | POWER | BLACKFIN | 3.3V | LATCH | FPGA_INIT | FMC | PG_C2M | PG_M2C | SWITCH | GPIO | FPGA PWR GD | RESET | BF | STATUS | CLK | CLK_N | TRIG | FAN | +12VDC | ON | USB | DDR3 MEMORY NOT INSTALLED | REV B | ADS7-V2EBZ
PAGE_OUTLINE: B | MINOR MODIFICATIONS | 28FEB14 | E.W.
DIMENSION: CUTOUT | SEE NOTE 15
User.9: L2 GROUND
User.10: L3 SIGNAL
User.11: L4 GROUND
User.12: L5 SIGNAL
User.13: L6 GROUND
User.14: L7 SIGNAL
User.15: L8 GROUND
User.16: L9 SIGNAL
User.17: L10 GROUND
User.18: L11 POWER
User.19: L12 POWER
User.20: L13 POWER
User.21: L14 POWER
User.22: L15 GROUND
User.23: L16 SIGNAL
User.24: L17 GROUND
User.25: L18 SIGNAL
User.26: L19 GROUND
User.27: DIFFERENTIAL IMPEDANCE =  100 OHMS +/- 10% | ARTWORK LINE WIDTH FOR | IMPEDANCE CONTROLLED LINES = 0.004 EXTERNAL AND 0.00350 INTERNAL | CHARACTERISTIC IMPEDANCE = 40 OHMS +/- 10% | IMPEDANCE CONTROLLED LINES = 0.0077 EXTERNAL AND 0.0055 INTERNAL | DIFFERENTIAL IMPEDANCE =  80 OHMS +/- 10% | IMPEDANCE CONTROLLED LINES = 0.006 EXTERNAL AND 0.0051 INTERNAL | GROUND PLANE    (LAYER 8) | GROUND PLANE    (LAYER 17) | INTERNAL SIGNAL (LAYER 18) | GROUND PLANE    (LAYER 19) | INTERNAL SIGNAL (LAYER 20) | GROUND PLANE    (LAYER 21) | INTERNAL SIGNAL (LAYER 22) | GROUND PLANE    (LAYER 23) | 0.0037" | 0.003" | 0.00527" | 0.0025" | 0.00346" | 0.00316" | 0.005" | 0.00361"
User.31: L21 GROUND
User.32: L20 SIGNAL
User.33: L22 SIGNAL
User.34: L23 GROUND
User.43: 3 | LAYER 24 TO L6 | BACKDRILL LOCATIONS
User.44: 4 | LAYER 24 TO L8 | BACKDRILL LOCATIONS
User.45: FAN AREA KEEPOUT | 5 | 6 | P2 KEEPOUT | P1 KEEPOUT | (0.080 THICK) | FIGURE | SIZE | 10.0 | 12.0 | 13.0 | 20.0 | 22.0 | 40.0 | 45.0 | 63.0 | 65.0 | 70.0 | 75.0 | 95.0 | 106.0 | 31.0 | 43.0 | 50.0 | 115.0 | 118.0 | PLATED | NON-PLATED | FINISHED HOLES IN MILS | ALL UNITS ARE IN MILS | QTY | 20 | 24 | 3374 | 1443 | 76 | 72 | 13 | 36 | 7 | 2 | 30 | TOLERANCE/NOTES | LAYER 24 TO L10 | LAYER 24 TO L19 | BACKDRILL LOCATIONS
